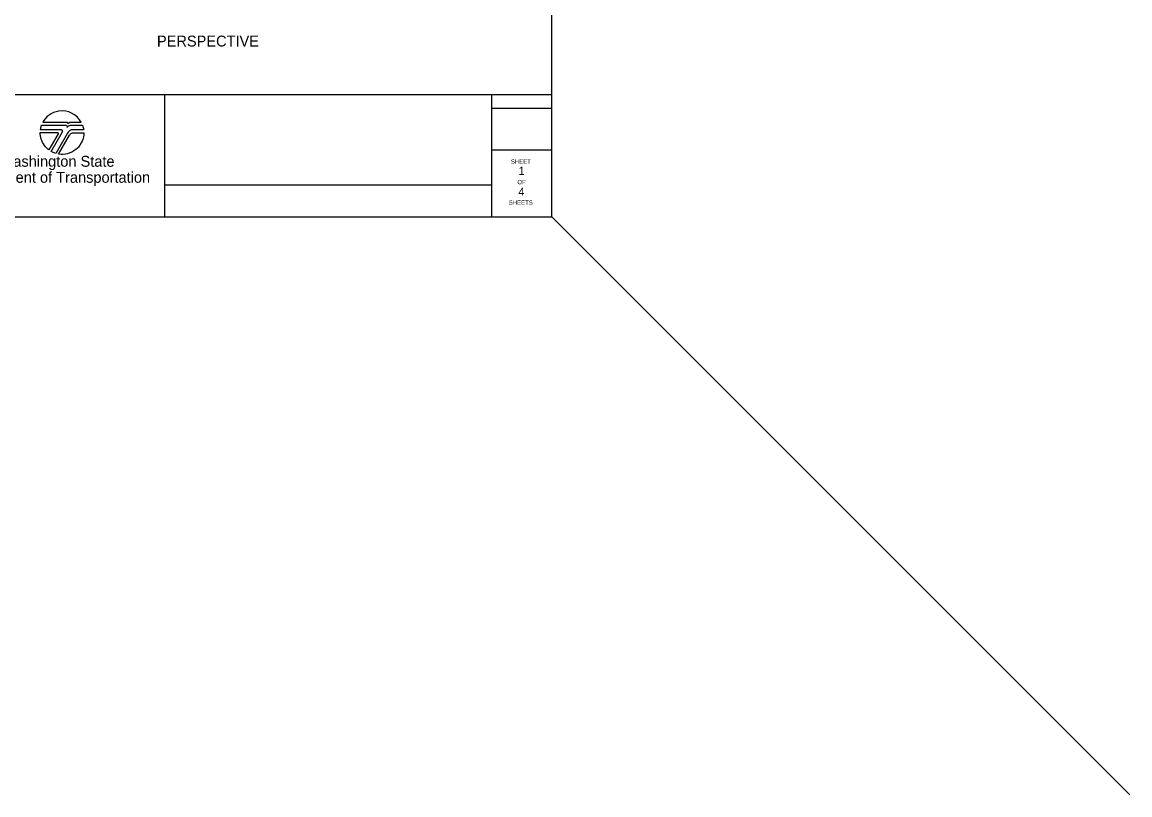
# Model space of a CAD drawing. Extents: x 99862 to 104211, y 98939 to 111076.
# Drawn here: x 102178 to 104211, y 98939 to 100358 of the extents above; entities that cross this region are included whole.
import ezdxf

# ---------------------------------------------------------------- set-up
doc = ezdxf.new("R2010")
doc.units = 0
for name, color, linetype in [('Level 1', 7, 'Continuous'), ('Level 20', 7, 'Continuous'), ('Level 60', 7, 'Continuous'), ('SH_GI_SheetLocationText', 7, 'Continuous')]:
    doc.layers.add(name, color=color, linetype=linetype)

msp = doc.modelspace()

# ---------------------------------------------------------------- linework, layer by layer
at = {"layer": 'Level 1'}
msp.add_line((103150, 100000), (104210.7, 98939.3), dxfattribs=at)
at = {"layer": 'Level 60'}
for p, q in [((103150, 100000), (103150, 102075)), ((100000, 100225), (103150, 100225)), ((102439.1, 100225), (102439.1, 100000)), ((103039.1, 100225), (103039.1, 100000)), ((103039.1, 100200), (103150, 100200)), ((103039.1, 100123.4), (103150, 100123.4)), ((102439.1, 100059.1), (103039.1, 100059.1)), ((100000, 100000), (103150, 100000))]:
    msp.add_line(p, q, dxfattribs=at)
for points in [[(102215.6, 100173.9), (102259.9, 100173.9), (102260.7, 100173.7), (102261.4, 100173.2), (102261.7, 100172.6), (102261.7, 100172), (102261.5, 100171.2), (102262.3, 100172.2), (102263.5, 100173.1), (102265.2, 100173.8), (102266.4, 100173.9), (102285.9, 100173.9), (102283, 100178.5), (102278.9, 100183.3), (102273.7, 100187.6), (102268.3, 100190.8), (102263.3, 100192.8), (102257.6, 100194.2), (102251.6, 100194.8), (102245.1, 100194.4), (102239.7, 100193.3), (102235.1, 100191.6), (102231.1, 100189.6), (102227.3, 100187.2), (102223.7, 100184.3), (102219.8, 100180.1), (102217.5, 100176.9)], [(102215.6, 100173.9), (102259.9, 100173.9), (102260.7, 100173.7), (102261.4, 100173.2), (102261.7, 100172.6), (102261.7, 100172), (102261.5, 100171.2), (102262.3, 100172.2), (102263.5, 100173.1), (102265.2, 100173.8), (102266.4, 100173.9), (102285.9, 100173.9), (102283, 100178.5), (102278.9, 100183.3), (102273.7, 100187.6), (102268.3, 100190.8), (102263.3, 100192.8), (102257.6, 100194.2), (102251.6, 100194.8), (102245.1, 100194.4), (102239.7, 100193.3), (102235.1, 100191.6), (102231.1, 100189.6), (102227.3, 100187.2), (102223.7, 100184.3), (102219.8, 100180.1), (102217.5, 100176.9)], [(102210.8, 100154.8), (102242.3, 100154.8), (102242.7, 100154.8), (102243.2, 100154.6), (102243.5, 100154.4), (102243.7, 100154.1), (102243.9, 100153.7), (102243.9, 100153.3), (102243.9, 100152.9), (102243.7, 100152.4), (102226.6, 100123), (102224.5, 100124.7), (102222.6, 100126.5), (102220.7, 100128.5), (102218.3, 100131.5), (102216.6, 100134.1), (102215, 100137), (102213.6, 100140.2), (102212.6, 100143), (102211.8, 100146), (102211.2, 100149), (102210.9, 100152)], [(102213.3, 100168.7), (102257.2, 100168.7), (102257.9, 100168.6), (102258.5, 100168.4), (102258.9, 100168.2), (102259.2, 100167.9), (102259.7, 100167.3), (102260, 100166.6), (102260.2, 100165.9), (102260.1, 100165.2), (102260, 100164.7), (102259.7, 100164.2), (102260.2, 100164.9), (102261.1, 100165.9), (102262.1, 100166.8), (102263.4, 100167.6), (102264.6, 100168.1), (102266.5, 100168.6), (102269.2, 100168.7), (102288.3, 100168.7), (102289.1, 100166.2), (102289.6, 100164.5), (102290, 100162.7), (102290.3, 100160.9), (102290.4, 100160.1), (102272, 100160.1), (102269.5, 100160), (102267.7, 100159.7), (102265.2, 100158.7), (102263.2, 100157.2), (102261.8, 100155.7), (102260.6, 100153.7), (102239.1, 100116.6), (102236.5, 100117.5), (102234.2, 100118.5), (102232.2, 100119.5), (102230.7, 100120.3), (102251.5, 100156.1), (102251.9, 100157.4), (102251.6, 100158.6), (102250.7, 100159.6), (102249.9, 100160), (102249.3, 100160.1), (102211.2, 100160.1), (102211.6, 100162.6), (102211.8, 100163.9), (102212.2, 100165.3), (102212.7, 100167)], [(102244.2, 100115.4), (102264.2, 100150), (102264.8, 100150.9), (102265.4, 100151.6), (102266.3, 100152.5), (102267.2, 100153.2), (102268.3, 100153.8), (102269.5, 100154.3), (102270.8, 100154.6), (102271.5, 100154.7), (102272.4, 100154.7), (102290.8, 100154.7), (102290.5, 100150.3), (102290, 100146.9), (102288.8, 100142.5), (102287.6, 100139.3), (102286, 100135.9), (102283.5, 100131.9), (102280.8, 100128.4), (102278.9, 100126.4), (102276.1, 100123.9), (102272.7, 100121.4), (102268.7, 100119.1), (102265, 100117.5), (102260.9, 100116.2), (102256.9, 100115.3), (102252.4, 100114.9), (102249.2, 100114.9), (102246.3, 100115.1)]]:
    msp.add_lwpolyline(points, close=True, dxfattribs=at)

# ---------------------------------------------------------------- texts
at = {"layer": 'Level 20'}
msp.add_text('PERSPECTIVE', height=20, rotation=360, dxfattribs=at).set_placement((102425, 100312.9))
at = {"layer": 'Level 60'}
for s, height, p in [('Washington State', 19.999, (102136.1, 100092.2)), ('SHEET', 8, (103074.6, 100097.8)), ('Department of Transportation', 19.999, (102063.1, 100062.8)), ('OF', 8, (103086.6, 100060.1)), ('SHEETS', 8, (103070.6, 100022.4))]:
    msp.add_text(s, height=height, dxfattribs=at).set_placement(p)
at = {"layer": 'SH_GI_SheetLocationText'}
for s, p in [('1', (103088.8, 100077.2)), ('4', (103088.4, 100039))]:
    msp.add_text(s, height=15, dxfattribs=at).set_placement(p)

doc.saveas('drawing.dxf')
